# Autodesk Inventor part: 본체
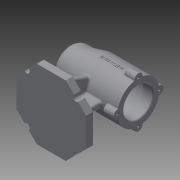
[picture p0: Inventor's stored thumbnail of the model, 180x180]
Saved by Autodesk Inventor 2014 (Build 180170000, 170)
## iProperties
Created: 2021-01
Part Number: 본체
Material: Generic
Document SubType Name: Modeling
Designer: kh
Density: 1 g/cm^3
Appearance: Default
Author: kh
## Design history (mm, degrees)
sketch "Sketch1"
  geometry: L1 (-20.711, 50)-(20.711, 50); L2 (20.711, 50)-(50, 20.711); L3 (50, 20.711)-(50, -20.711); L4 (50, -20.711)-(20.711, -50); L5 (20.711, -50)-(-20.711, -50); L6 (-20.711, -50)-(-50, -20.711); L7 (-50, -20.711)-(-50, 20.711); L8 (-50, 20.711)-(-20.711, 50); 2 further points
  constraints: 16 end point, 1 coincident, 1 horizontal, 17 other
  dimensions: "d0" = 50 distance from line of L3 point (0, 0)
extrude "Extrusion1" new body sketch "Sketch1" distance "d1" = 10; taper "d2" = 0 deg
sketch "Sketch3"
  geometry: L1 (0, 0)-(0, 32.527); L2 (-50, 75)-(50, 75); L3 (-50, 75)-(-50, 100); L4 (-50, 100)-(-30, 100); L5 (-30, 100)-(-10, 105); L6 (-10, 105)-(50, 105); L7 (50, 105)-(50, 75); L8 (-20.711, 0)-(20.711, 0) reference; L9 (50, 0)-(50, 10) reference; L10 (-44, 75)-(-44, 85.5); L11 (-44, 85.5)-(-41, 85.5); L12 (-41, 85.5)-(-41, 91); L13 (-41, 91)-(-37, 91); L14 (-37, 91)-(-37, 92.5); L15 (-37, 92.5)-(-19, 92.5); L16 (35, 99)-(35, 96); L17 (35, 96)-(50, 96); L18 (-19, 92.5)-(-19, 96); L19 (-19, 96)-(-7, 96); L20 (-7, 96)-(-7, 99); L21 (-7, 99)-(35, 99)
  constraints: 38 end point, 8 perpendicular, 7 parallel, 2 point on line, 1 collinear, 1 horizontal, 1 vertical
  dimensions: "d3" = 60 diameter of L6 L2; "d4" = 20 distance from line of L4.end L3; "d5" = 40 distance from line of L5.end L3; "d6" = 100 distance between parallel lines of L7 L3; "d7" = 75 distance between parallel lines of L8 L2; "d8" = 50 diameter of L4 L2; "d9" = 21 diameter of L11 L2; "d10" = 32 diameter of L13 L2; "d11" = 35 diameter of L15 L2; "d12" = 42 diameter of L19 L2; "d13" = 48 diameter of L21 L2; "d14" = 42 diameter of L17 L2; "d15" = 15 distance between parallel lines of L16 L7; "d16" = 42 distance between parallel lines of L20 L16; "d17" = 12 distance between parallel lines of L18 L20; "d18" = 18 distance between parallel lines of L14 L18; "d19" = 4 distance between parallel lines of L12 L14; "d20" = 3 distance between parallel lines of L10 L12
revolve "Revolution1" sketch "Sketch3" stored, may be unused: angle "d21" = 90 deg
sketch "Sketch5"
  geometry: L1 (20.711, 10)-(-20.711, 10) reference; L2 (-20.711, 10)-(-50, 10) reference; L3 (50, 10)-(20.711, 10) reference; L4 (-27, 10)-(-21.119, 40.257); L5 (-50, 0)-(-50, 10) reference; L6 (27, 10)-(27, 36.527); L7 (50, 0)-(50, 10) reference; 1 further point
  constraints: 4 end point, 2 point on line, 1 parallel
  dimensions: "d22" = 23 distance from line of L5 L4.start; "d23" = 101 deg angle of L4 L2; "d30" = 23 distance from line of L7 L6.start
feature "Rib1" dims "d24" = 1, "d25" = 8, "d26" = 0, "d27" = 0, "d28" = 1, "d29" = 1
feature "Rib2" dims "d31" = 1, "d32" = 8, "d33" = 0, "d34" = 0, "d35" = 1, "d36" = 1
sketch "Sketch6"
  geometry: L1 (10, 20.711)-(10, 50) reference; L2 (10, 35)-(32.836, 26.688); L3 (0, 50)-(10, 50) reference; L4 (10, -50)-(10, -20.711) reference; L5 (10, -35)-(35.757, -25.625); L6 (0, -50)-(10, -50) reference; 1 further point
  constraints: 4 end point, 2 point on line
  dimensions: "d37" = 15 distance from line of L3 L2.start; "d38" = 110 deg angle of L1 L2; "d45" = 15 distance from line of L6 L5.start; "d46" = 110 deg angle of L4 L5
feature "Rib3" dims "d39" = 1, "d40" = 8, "d41" = 0, "d42" = 0, "d43" = 1, "d44" = 1
feature "Rib4" dims "d47" = 1, "d48" = 8, "d49" = 0, "d50" = 0, "d51" = 1, "d52" = 1
sketch "Sketch7"
  geometry: L1 (-35.355, 35.355)-(35.355, -35.355); L2 (-35.355, -35.355)-(35.355, 35.355); L3 (-50, 0)-(50, 0); A1 r 50 centre (0, 0) between (-35.355, 35.355) and (35.355, -35.355); 6 further points
  constraints: 6 end point, 6 point on circle, 5 coincident, 3 midpoint, 1 centre point, 1 horizontal
  dimensions: "d53" = 100 diameter of A1; "d55" = 45 deg angle of L3 L1; "d56" = 45 deg angle of L2 L3
hole "Hole1" sketch "Sketch7" at (-35.355, 35.355), (35.355, 35.355), (35.355, -35.355), (-35.355, -35.355) diameter "d57" = 9; stored, may be unused: countersink angle "d61" = 90 deg, drill point angle "d63" = 0 deg; dims "d58" = 6, "d59" = 4, "d60" = 2, "d62" = 8
sketch "Sketch8"
  geometry: L1 (0, -30)-(0, 30); A1 r 30 centre (0, 0) between (0, -30) and (0, 30) reference; A2 r 6 centre (0, 30) between (5.97, 29.4) and (-5.97, 29.4); A3 r 30 centre (0, 0) between (5.97, 29.4) and (-5.97, 29.4); 1 further point
  constraints: 9 point on circle, 2 centre point, 2 end point, 1 coincident, 1 midpoint, 1 vertical
  dimensions: "d66" = 12 diameter of A2
extrude "Extrusion2" join sketch "Sketch8" distance "d67" = 16; taper "d68" = 0 deg
sketch "Sketch9"
  geometry: A1 r 6 centre (0, 0) between (5.97, -0.6) and (-5.97, -0.6) reference; 2 further points
  constraints: 1 coincident
hole "Hole2" sketch "Sketch9" at (0, 0) diameter "d69" = 3.459; stored, may be unused: countersink angle "d73" = 90 deg, drill point angle "d75" = 118 deg; dims "d70" = 8, "d71" = 4, "d72" = 2, "d74" = 10
pattern_circular "Circular Pattern1" dims angle "d77" = 360 deg
fillet "Fillet1" dims "d79" = 10
fillet "Fillet2" dims "d80" = 3
fillet "Fillet3" dims "d81" = 3
fillet "Fillet4" dims "d82" = 1
fillet "Fillet5" dims "d83" = 3
fillet "Fillet6" dims "d84" = 0.3
fillet "Fillet7" dims "d85" = 3
chamfer "Chamfer1" distance "d86" = 1; stored, may be unused: second distance "d87" = 2, angle "d88" = 45 deg
fillet "Fillet8" dims "d89" = 3
fillet "Fillet9" dims "d90" = 3
fillet "Fillet10" dims "d91" = 3
sketch "Sketch11"
  geometry: L1 (12.213, 82.916)-(53.209, 82.916); L2 (53.209, 82.916)-(53.209, 67.084); L3 (53.209, 67.084)-(12.213, 67.084); L4 (12.213, 67.084)-(12.213, 82.916); L5 (12.213, 75)-(53.209, 75); L6 (70.711, 81.771)-(70.711, 104.226) reference; L7 (-29.289, 60)-(-29.289, 90) reference; 3 further points
  constraints: 4 midpoint, 2 end point, 1 point on line, 2 other
  dimensions: "d92" = 38 distance from line of L6 point (32.711, 75)
emboss "Emboss1" sketch "Sketch11" dims "d93" = 0.5, "d94" = 0
body "Solid1"
